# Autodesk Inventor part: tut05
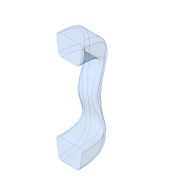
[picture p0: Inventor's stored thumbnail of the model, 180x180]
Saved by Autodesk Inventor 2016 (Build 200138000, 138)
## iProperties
Created: 2015-03
Part Number: tut05
Material: Generic
Document SubType Name: Modeling
Designer: Sandeep
Density: 1 g/cm^3
Appearance: Blue - Glazing
Author: Sandeep
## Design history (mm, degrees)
sketch "Sketch1"
  geometry: L1 (-20, 50)-(20, 50); L2 (30, 60)-(30, 70); L3 (-30, 60)-(-30, 70); L4 (0, -9.695)-(0, 120.745); A1 r 45 centre (0, 36.459) between (30, 70) and (-30, 70); A2 r 10 centre (-20, 60) between (-30, 60) and (-20, 50); A3 r 10 centre (20, 60) between (20, 50) and (30, 60); 2 further points
  constraints: 8 end point, 6 point on circle, 4 point on line, 4 tangent, 3 centre point, 2 vertical, 1 horizontal, 1 perpendicular, 1 other
  dimensions: "d0" = 60 distance between parallel lines of L2 L3; "d1" = 70 vertical distance of point (0, 0) L2.end; "d2" = 20 distance of point (30, 50) L2.end; "d3" = 45 radius of A1; "d4" = 10 radius of A2; "d5" = 10 radius of A3
sketch "Sketch2"
  geometry: L1 (30.844, 175)-(-30.844, 175); L2 (-40.728, 163.479)-(-33.805, 118.479); L3 (-23.921, 110)-(23.921, 110); L4 (33.805, 118.479)-(40.728, 163.479); L5 (0, 0)-(0, 325.346); A1 r 10 centre (30.844, 165) between (40.728, 163.479) and (30.844, 175); A2 r 10 centre (-30.844, 165) between (-30.844, 175) and (-40.728, 163.479); A3 r 10 centre (-23.921, 120) between (-33.805, 118.479) and (-23.921, 110); A4 r 10 centre (23.921, 120) between (23.921, 110) and (33.805, 118.479); 4 further points
  constraints: 10 end point, 8 point on circle, 8 point on line, 8 tangent, 4 centre point, 3 equal radius, 1 horizontal, 1 parallel, 1 vertical, 1 other
  dimensions: "d6" = 65 distance of point (-32.5, 110) point (32.5, 110); "d7" = 65 distance between parallel lines of L1 L3; "d8" = 85 distance of point (42.5, 175) point (-42.5, 175); "d9" = 175 distance from line of L5.start L1; "d10" = 10 radius of A1
sketch "Sketch3"
  geometry: 1 further point
sketch "Sketch4"
  geometry: 1 further point
sketch "Sketch5"
  geometry: L1 (30.844, -110)-(-30.844, -110); L2 (-40.728, -121.521)-(-33.805, -166.521); L3 (-23.921, -175)-(23.921, -175); L4 (33.805, -166.521)-(40.728, -121.521); L5 (0, 0)-(0, -235.653); A1 r 10 centre (-23.921, -165) between (-33.805, -166.521) and (-23.921, -175); A2 r 10 centre (23.921, -165) between (23.921, -175) and (33.805, -166.521); A3 r 10 centre (30.844, -120) between (40.728, -121.521) and (30.844, -110); A4 r 10 centre (-30.844, -120) between (-30.844, -110) and (-40.728, -121.521); 4 further points
  constraints: 10 end point, 8 point on circle, 8 point on line, 8 tangent, 4 centre point, 3 equal radius, 1 horizontal, 1 parallel, 1 vertical, 1 other
  dimensions: "d11" = 85 distance of point (42.5, -110) point (-42.5, -110); "d12" = 65 distance of point (-32.5, -175) point (32.5, -175); "d13" = 65 distance between parallel lines of L1 L3; "d14" = 175 distance from line of L5.start L3; "d15" = 10 radius of A1
loft "Loft1" sketch "Sketch5" dims "d16" = 50, "d17" = 90 deg, "d18" = 0, "d19" = 90 deg, "d20" = 50, "d21" = 90 deg
body "Solid1"
